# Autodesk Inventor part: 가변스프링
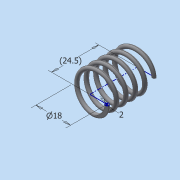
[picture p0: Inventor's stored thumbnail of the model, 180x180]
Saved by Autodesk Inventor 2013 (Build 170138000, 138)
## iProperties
Created: 2017-12
Part Number: 가변스프링
Material: 스테인리스강
Document SubType Name: Modeling
Designer: dgall
Density: 8.08 g/cm^3
Mass: 7.05284 g
Surface Area: 17.7159 cm^2
Volume: 0.872877 cm^3
Author: dgall
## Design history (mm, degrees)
sketch "스케치1"
  geometry: L1 (9, 0)-(0, 0); L2 (0, 0)-(0, 24.5); L3 (0, 24.5)-(9, 24.5); C1 r 1 at (9, 0)
  constraints: 6 end point, 2 parallel, 1 centre point, 1 coincident, 1 horizontal, 1 perpendicular
  dimensions: "d0" = 18 diameter of L1.start L2; "d2" = 24.5 distance of L1.end L2.end (derived); "d3" = 2 diameter of C1
feature "코일1" pitch "d4" = 10; turns "d6" = 5; dims "d5" = 24.5 (= d2), "d7" = 0, angle "d8" = 90 deg, angle "d9" = 90 deg, "d10" = 0, "d11" = 0
node "작업 평면1"
feature "분할1"
node "작업 평면2"
feature "분할2"
node "솔리드1"
other parameters: "d12" = 0, "d13" = 0
